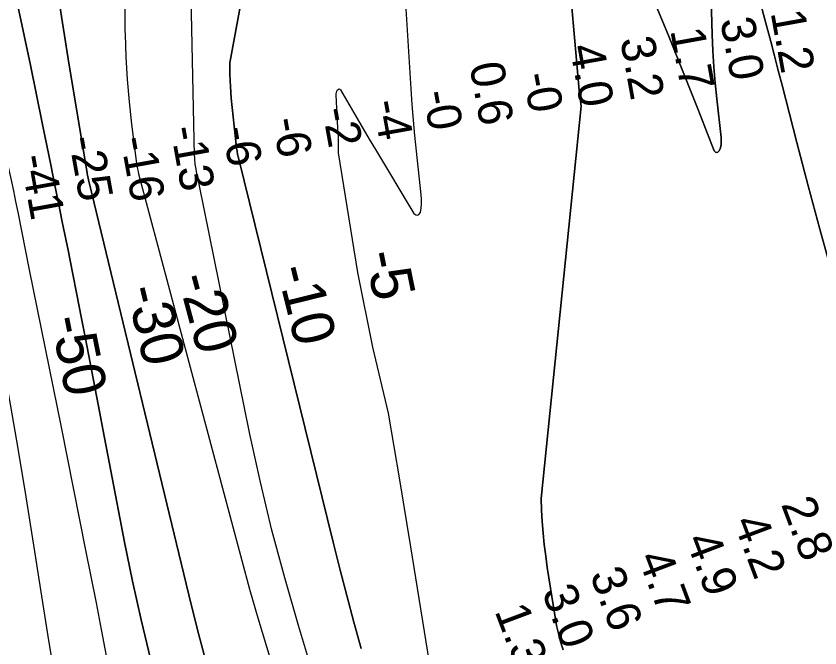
# Model space of a CAD drawing. Extents: x 3297753 to 3335611, y 652252 to 677623.
# Drawn here: x 3308796 to 3310374, y 672962 to 674202 of the extents above; entities that cross this region are included whole.
import ezdxf

# ---------------------------------------------------------------- set-up
doc = ezdxf.new("R2010")
doc.units = 0
for name, color, linetype in [('V-RIVR-EDGE', 7, 'Continuous'), ('V-RIVR-RANG', 7, 'Continuous'), ('V-TOPO-DPTH', 7, 'Continuous'), ('V-TOPO-MAJR', 7, 'Continuous'), ('V-TOPO-MAJR-IDEN', 7, 'Continuous'), ('V-TOPO-MINR', 7, 'Continuous'), ('V-TOPO-MINR-IDEN', 7, 'Continuous'), ('V-TOPO-WATR', 7, 'Continuous')]:
    doc.layers.add(name, color=color, linetype=linetype)

msp = doc.modelspace()

# ---------------------------------------------------------------- linework, layer by layer
at = {"layer": 'V-RIVR-EDGE'}
msp.add_spline([(3307850.6, 675821), (3307850.8, 675819.3), (3307852.4, 675798.5), (3307852.3, 675791.1), (3307856.9, 675791.5), (3307860.2, 675784), (3307858.1, 675766.6), (3307858, 675745.9), (3307859.7, 675743.8), (3307863.4, 675743), (3307863.4, 675739.6), (3307862.9, 675721), (3307866.2, 675694), (3307864.5, 675668.3), (3307864.8, 675653.4), (3307866, 675632.3), (3307866, 675608.2), (3307860.9, 675578), (3307855, 675536.2), (3307852, 675491), (3307848.6, 675457.4), (3307845.6, 675420.9), (3307843.1, 675401.9), (3307841.8, 675387.8), (3307842.2, 675364.6), (3307841.7, 675337.2), (3307844.1, 675320.6), (3307845.7, 675299.9), (3307849, 675263), (3307851.4, 675230.3), (3307851.7, 675205), (3307854.1, 675179.3), (3307857, 675154), (3307856.5, 675138.2), (3307855.7, 675135.8), (3307856.1, 675118.3), (3307855.6, 675111.7), (3307854.4, 675096), (3307852.6, 675077.7), (3307852.2, 675054.1), (3307855.4, 675031.7), (3307862.4, 674991.5), (3307864.8, 674962.5), (3307868.4, 674926), (3307870, 674906.1), (3307872.5, 674875), (3307874.1, 674859.3), (3307876.5, 674843.5), (3307878.9, 674816.1), (3307882.5, 674757.7), (3307886.1, 674712.5), (3307885.7, 674704.2), (3307884.5, 674698), (3307884.4, 674691.8), (3307887.3, 674680.2), (3307887.3, 674669), (3307887.3, 674658.2), (3307885.6, 674651.2), (3307881, 674644.1), (3307881, 674640), (3307886.3, 674626.3), (3307890, 674605.5), (3307895.8, 674578.6), (3307899.4, 674550.8), (3307909.3, 674510.6), (3307914.6, 674482), (3307918.3, 674453.8), (3307918.2, 674440.5), (3307919.9, 674433.9), (3307927.3, 674423.1), (3307927.3, 674417.7), (3307927.2, 674404), (3307928.5, 674400.3), (3307931.8, 674393.2), (3307935.1, 674376.6), (3307944.5, 674357.6), (3307954.9, 674337.2), (3307963.9, 674316.1), (3307975.4, 674271.7), (3307986.5, 674225.2), (3308000.1, 674178.8), (3308007.4, 674148.9), (3308015.2, 674108.3), (3308020.5, 674078.4), (3308024.2, 674072.2), (3308025, 674059.3), (3308025.4, 674039.4), (3308027.8, 673997.2), (3308030.6, 673971.5), (3308027.7, 673955.3), (3308027.2, 673943.3), (3308027.6, 673935.8), (3308029.7, 673925.4), (3308035.5, 673911.8), (3308035.4, 673899.3), (3308034.1, 673873.2), (3308036.1, 673851.2), (3308038.5, 673818.9), (3308041, 673799), (3308046.8, 673788.2), (3308050.5, 673778.3), (3308048.8, 673772.5), (3308048.8, 673761.3), (3308053.7, 673740.5), (3308060.7, 673711.1), (3308069.7, 673678.7), (3308069.7, 673665.1), (3308067.1, 673653.5), (3308067.6, 673650.1), (3308072.9, 673649.3), (3308077.9, 673648.9), (3308080, 673646.4), (3308086.5, 673608.6), (3308091.8, 673582.1), (3308104.6, 673536.5), (3308114.8, 673495), (3308121.4, 673461), (3308123.8, 673446.1), (3308128, 673436.1), (3308140.3, 673406.2), (3308148.9, 673377.2), (3308153, 673357.7), (3308158.3, 673321.2), (3308169, 673273.1), (3308189.1, 673188.1), (3308196.9, 673150.4), (3308208, 673103.9), (3308212, 673079.5), (3308214.1, 673060), (3308216.5, 673045), (3308219, 673035.9), (3308226, 673025.5), (3308228.5, 673016), (3308228.4, 673002.3), (3308230.5, 672996.9), (3308235, 672992.8), (3308235, 672984.5), (3308237.5, 672972.9), (3308242, 672953.4), (3308247.3, 672933.1), (3308253.9, 672910.7), (3308257.6, 672901.5), (3308263.8, 672890.3), (3308276.2, 672865), (3308277.4, 672856.3), (3308278.6, 672850.1), (3308283.2, 672844.3), (3308286.1, 672839.7), (3308286, 672832.2), (3308285.6, 672819), (3308288.5, 672812.3), (3308293.8, 672800.3), (3308303.7, 672777.9), (3308309.9, 672762.5), (3308316.1, 672743), (3308316.4, 672725.6), (3308318.1, 672723.1), (3308323.1, 672717.3), (3308327.6, 672706.1), (3308331.7, 672690.4), (3308330.8, 672679.6), (3308330.4, 672672.1), (3308332.5, 672667.2), (3308337.4, 672658.4), (3308343.6, 672642.7), (3308347.7, 672625.3), (3308355.9, 672595.4), (3308355.9, 672584.6), (3308357.5, 672579.6), (3308362.1, 672570.9), (3308366.6, 672563.5), (3308376.1, 672534), (3308399.6, 672478.4), (3308411.5, 672452.7), (3308418.5, 672435.2), (3308421.8, 672418.7), (3308423, 672410), (3308425.5, 672403.7), (3308428.8, 672397.5), (3308430, 672387.6), (3308434.9, 672375.5), (3308444.4, 672344.8), (3308450.6, 672327), (3308456.8, 672320.8), (3308459.7, 672312.9), (3308465.4, 672288), (3308467.4, 672268.1), (3308473.2, 672249), (3308476.1, 672236.6), (3308485.9, 672214.2), (3308490.1, 672198.8), (3308495.9, 672201.7), (3308496.7, 672193), (3308499.1, 672161.9), (3308505.2, 672134.5), (3308513.9, 672107.6), (3308522.5, 672084.8), (3308527.9, 672082.3), (3308536.2, 672087.2), (3308540.8, 672086.8), (3308539.5, 672083.9), (3308535.8, 672077.7), (3308534.9, 672067.7), (3308534.5, 672059.4), (3308532, 672050.7), (3308533.2, 672047.4), (3308536.9, 672037.9), (3308550.9, 672008.4), (3308564.9, 671974.4), (3308569.9, 671959.5), (3308576.5, 671954.9), (3308585.1, 671932.5), (3308595.9, 671910.5), (3308604.9, 671895.1), (3308605.8, 671888.5), (3308607.8, 671885.2), (3308610.7, 671881), (3308616.5, 671862.8), (3308627.6, 671838.7), (3308640.4, 671816.3), (3308661, 671765.3), (3308673, 671740.8), (3308685.3, 671715.5), (3308698.5, 671692.2), (3308700.2, 671685.6), (3308711.3, 671658.2), (3308728.2, 671627.9), (3308743.1, 671603), (3308758.3, 671575.6), (3308772, 671554.8), (3308775.3, 671548.6), (3308783.1, 671536.2), (3308790.5, 671522.9), (3308793.4, 671519.6), (3308797.2, 671517.1), (3308801.3, 671511.2), (3308803.8, 671502.9), (3308810.8, 671502.1), (3308815.8, 671499.2), (3308833.5, 671474.3), (3308845.1, 671458.5), (3308857.1, 671443.5), (3308870.7, 671429), (3308882.7, 671418.6), (3308908.8, 671397), (3308930.3, 671375.4), (3308944.3, 671361.3), (3308952.6, 671346.7), (3308960.4, 671336.8), (3308966.2, 671331.8), (3308972.8, 671328.9), (3308985.6, 671307.3), (3309001.7, 671282.4), (3309010.8, 671271.6), (3309010.8, 671268.3), (3309008.3, 671266.2), (3309011.6, 671262), (3309018.7, 671250.8), (3309024.8, 671237.1), (3309035.1, 671212.2), (3309059.5, 671169.1), (3309066.5, 671150.8), (3309067.7, 671140.5), (3309071.8, 671135.9), (3309077.2, 671128.4), (3309078.4, 671123), (3309078.4, 671117.6), (3309082.1, 671111.4), (3309089.1, 671092.7), (3309098.6, 671073.2), (3309111.4, 671045), (3309116.4, 671032.2), (3309123.3, 671011), (3309128.7, 670995.6), (3309133.2, 670984.9), (3309144, 670967.4), (3309159.7, 670945.4), (3309169.2, 670933.4), (3309182, 670924.2), (3309188.2, 670917.2), (3309197.7, 670902.2), (3309217.1, 670874.8), (3309231.6, 670859), (3309239.8, 670845.3), (3309244.8, 670840.8), (3309252.2, 670835.3), (3309260.5, 670831.2), (3309275.4, 670817.1), (3309282.4, 670810.4), (3309290.7, 670800), (3309303.1, 670788.4), (3309315.9, 670775.5), (3309335.3, 670751), (3309344.4, 670736.5), (3309351, 670726.5), (3309360.1, 670721.5), (3309375.8, 670704.9), (3309390.7, 670688.7), (3309403.1, 670668.8), (3309415.5, 670646.8), (3309426.7, 670635.1), (3309442.8, 670618.5), (3309454.3, 670603.2), (3309462.2, 670588.6), (3309470.9, 670575.3), (3309476.6, 670563.3), (3309487.4, 670558.3), (3309488.6, 670554.6), (3309489.4, 670550.8), (3309494.8, 670544.2), (3309506.8, 670533.4), (3309523.8, 670518.8), (3309530, 670506), (3309538.6, 670484.8), (3309549.7, 670453.7), (3309551.3, 670440.9), (3309555.5, 670430.9), (3309568.7, 670408.9), (3309577.3, 670396), (3309581.5, 670386.5), (3309581.5, 670383.2), (3309578.6, 670379.9), (3309576.9, 670374.9), (3309582.2, 670364.1), (3309594.6, 670336.7), (3309604.5, 670308.9), (3309606.9, 670296.1), (3309614.4, 670284.8), (3309627.2, 670267), (3309635.5, 670261.6), (3309639.2, 670259.9), (3309638.7, 670250), (3309639.5, 670236.3), (3309641.2, 670228), (3309644.9, 670221.4), (3309656.5, 670208.1), (3309664.3, 670195.6), (3309663.5, 670188.2), (3309663.8, 670176.1), (3309668, 670166.2), (3309673.3, 670159.9), (3309684.1, 670142.9), (3309690.7, 670126.3), (3309700.1, 670102.7), (3309716.7, 670076.5)], degree=3, dxfattribs=at)
at = {"layer": 'V-TOPO-DPTH'}
for points in [[(3309390.6, 675056.3), (3309215.6, 674110.2), (3309215.8, 674087.1), (3309216.9, 674064), (3309218.8, 674040.9), (3309228.3, 673949.2), (3309229, 673942.9), (3309230, 673936.6), (3309231.2, 673930.3), (3309232.6, 673924.1), (3309418.4, 673169.5), (3309431.6, 673117.2), (3309445.2, 673065), (3309459.4, 673013), (3309473.9, 672961.1)], [(3309473.9, 672961.1), (3309459.4, 673013), (3309445.2, 673065), (3309431.6, 673117.2), (3309418.4, 673169.5), (3309232.6, 673924.1), (3309231.2, 673930.3), (3309230, 673936.6), (3309229, 673942.9), (3309228.3, 673949.2), (3309218.8, 674040.9), (3309216.9, 674064), (3309215.8, 674087.1), (3309215.6, 674110.2), (3309390.6, 675056.3)], [(3310397.2, 673699), (3310373.8, 673783.7), (3310351.1, 673868.6), (3310328.8, 673953.6), (3310299.8, 674066.4), (3310292.4, 674095.1), (3310284.9, 674123.7), (3310277.4, 674152.3), (3310269.7, 674180.9), (3310198.5, 674446), (3310194.5, 674455.8), (3310189.2, 674464.6), (3310181.9, 674471.9), (3310173.2, 674478.1), (3310166.2, 674479), (3310160.4, 674477.7), (3310156.7, 674473.2), (3310154.3, 674466.5), (3310162.6, 674165.7), (3310163.9, 674134), (3310165.7, 674102.4)], [(3310165.7, 674102.4), (3310163.9, 674134), (3310162.6, 674165.7), (3310154.3, 674466.5), (3310156.7, 674473.2), (3310160.4, 674477.7), (3310166.2, 674479), (3310173.2, 674478.1), (3310181.9, 674471.9), (3310189.2, 674464.6), (3310194.5, 674455.8), (3310198.5, 674446), (3310269.7, 674180.9), (3310277.4, 674152.3), (3310284.9, 674123.7), (3310292.4, 674095.1), (3310299.8, 674066.4), (3310328.8, 673953.6), (3310351.1, 673868.6), (3310373.8, 673783.7), (3310397.2, 673699)], [(3310165.7, 674102.4), (3310168.4, 674070.9), (3310171.6, 674039.4), (3310180.2, 673963.5), (3310180.5, 673956.8), (3310180, 673950.2), (3310178.6, 673943.7), (3310176.5, 673937.3), (3310173.9, 673935), (3310171.3, 673934), (3310168.8, 673935), (3310166.3, 673937.5), (3310134.3, 674019.7), (3310120.2, 674055.8), (3310105.9, 674091.9), (3310091.3, 674127.8), (3310076.6, 674163.7), (3310016.2, 674310.2)], [(3310016.2, 674310.2), (3310076.6, 674163.7), (3310091.3, 674127.8), (3310105.9, 674091.9), (3310120.2, 674055.8), (3310134.3, 674019.7), (3310166.3, 673937.5), (3310168.8, 673935), (3310171.3, 673934), (3310173.9, 673935), (3310176.5, 673937.3), (3310178.6, 673943.7), (3310180, 673950.2), (3310180.5, 673956.8), (3310180.2, 673963.5), (3310171.6, 674039.4), (3310168.4, 674070.9), (3310165.7, 674102.4)], [(3309880.2, 674301), (3309898.6, 674086.2), (3309900, 674070.9), (3309901.6, 674055.7), (3309903.5, 674040.5), (3309905.5, 674025.3), (3309827.1, 673255.3), (3309827.9, 673232.7), (3309829.1, 673210), (3309830.9, 673187.4), (3309833.1, 673164.8), (3309835.8, 673142.3), (3309839, 673119.8), (3309854.1, 673022.6), (3309857.1, 673006.3), (3309860.7, 672990.2), (3309865.2, 672974.3), (3309870.3, 672958.5)], [(3309870.3, 672958.5), (3309865.2, 672974.3), (3309860.7, 672990.2), (3309857.1, 673006.3), (3309854.1, 673022.6), (3309839, 673119.8), (3309835.8, 673142.3), (3309833.1, 673164.8), (3309830.9, 673187.4), (3309829.1, 673210), (3309827.9, 673232.7), (3309827.1, 673255.3), (3309905.5, 674025.3), (3309903.5, 674040.5), (3309901.6, 674055.7), (3309900, 674070.9), (3309898.6, 674086.2), (3309880.2, 674301)], [(3308880.3, 674235.4), (3308898.3, 674118.3), (3308935.9, 673894), (3308936.8, 673889.3), (3308937.7, 673884.7), (3308938.7, 673880.1), (3308939.7, 673875.5), (3309125.3, 673107.2), (3309140, 673047.6), (3309155.1, 672988.1), (3309170.8, 672928.8)], [(3309170.8, 672928.8), (3309155.1, 672988.1), (3309140, 673047.6), (3309125.3, 673107.2), (3308939.7, 673875.5), (3308938.7, 673880.1), (3308937.7, 673884.7), (3308936.8, 673889.3), (3308935.9, 673894), (3308898.3, 674118.3), (3308880.3, 674235.4)], [(3308800, 674222.2), (3308812.3, 674164.1), (3308824.4, 674105.9), (3308836.3, 674047.7), (3308848.2, 673989.5), (3308856.7, 673947.7), (3308864.3, 673910.3), (3308871.8, 673873), (3308879.4, 673835.7), (3308887, 673798.4), (3308889.5, 673786), (3308898.4, 673742.5), (3308907.1, 673698.9), (3308915.7, 673655.4), (3308924.2, 673611.8), (3308932.5, 673569.3), (3308945.1, 673504.4), (3308957.6, 673439.6), (3308970.1, 673374.7), (3308982.6, 673309.8), (3309009.4, 673170), (3309024.9, 673093.4), (3309041.7, 673017), (3309060.1, 672941.1)], [(3309060.1, 672941.1), (3309041.7, 673017), (3309024.9, 673093.4), (3309009.4, 673170), (3308982.6, 673309.8), (3308970.1, 673374.7), (3308957.6, 673439.6), (3308945.1, 673504.4), (3308932.5, 673569.3), (3308924.2, 673611.8), (3308915.7, 673655.4), (3308907.1, 673698.9), (3308898.4, 673742.5), (3308889.5, 673786), (3308887, 673798.4), (3308879.4, 673835.7), (3308871.8, 673873), (3308864.3, 673910.3), (3308856.7, 673947.7), (3308848.2, 673989.5), (3308836.3, 674047.7), (3308824.4, 674105.9), (3308812.3, 674164.1), (3308800, 674222.2)], [(3309305.7, 672908.4), (3309288.2, 672964.4), (3309271.4, 673020.5), (3309255.3, 673076.9), (3309239.8, 673133.4), (3309037.5, 673891.7), (3309036.3, 673896.8), (3309035.1, 673902), (3309034.2, 673907.2), (3309033.5, 673912.4), (3309023.6, 673989.7), (3309018.7, 674033.7), (3309014.8, 674077.7), (3309012.4, 674121.8), (3309010.9, 674166), (3309010.7, 674172.8), (3309010.4, 674220.4)], [(3309305.7, 672908.4), (3309288.2, 672964.4), (3309271.4, 673020.5), (3309255.3, 673076.9), (3309239.8, 673133.4), (3309037.5, 673891.7), (3309036.3, 673896.8), (3309035.1, 673902), (3309034.2, 673907.2), (3309033.5, 673912.4), (3309023.6, 673989.7), (3309018.7, 674033.7), (3309014.8, 674077.7), (3309012.4, 674121.8), (3309010.9, 674166), (3309010.7, 674172.8), (3309010.4, 674220.4)]]:
    msp.add_lwpolyline(points, dxfattribs=at)
at = {"layer": 'V-TOPO-MAJR'}
msp.add_lwpolyline([(3308973.8, 672946.4), (3308963.9, 672998.4), (3308953.9, 673050.4), (3308943.7, 673102.3), (3308933.4, 673154.2), (3308885.2, 673395.2), (3308869.7, 673472.5), (3308854.2, 673549.8), (3308838.6, 673627), (3308823, 673704.3), (3308800.3, 673817), (3308796, 673837.9), (3308791.7, 673858.8), (3308787.2, 673879.7), (3308782.6, 673900.5), (3308753, 674033.4), (3308733, 674120.6), (3308712.4, 674207.6)], dxfattribs=at)
at = {"layer": 'V-TOPO-MINR'}
for points in [[(3309473.9, 672961.1), (3309459.4, 673013), (3309445.2, 673065), (3309431.6, 673117.2), (3309418.4, 673169.5), (3309232.6, 673924.1), (3309231.2, 673930.3), (3309230, 673936.6), (3309229, 673942.9), (3309228.3, 673949.2), (3309218.8, 674040.9), (3309216.9, 674064), (3309215.8, 674087.1), (3309215.6, 674110.2), (3309390.6, 675056.3)], [(3309611.3, 672913.3), (3309571.4, 673160.7), (3309549.8, 673291.9), (3309527.6, 673423), (3309496.4, 673552.4), (3309466.9, 673698.9), (3309429, 673933.4), (3309429.3, 673966.3), (3309428.6, 673971.8), (3309428, 673977.3), (3309427.6, 673982.8), (3309424.4, 674046.5), (3309424.5, 674049.4), (3309425, 674052.1), (3309425.9, 674054.8), (3309427.2, 674057.4), (3309430.3, 674059), (3309431.8, 674058.5), (3309433.3, 674057.2), (3309453.8, 674021.4), (3309465.6, 674000.9), (3309477.4, 673980.6), (3309489.4, 673960.2), (3309501.5, 673940), (3309577, 673814.3), (3309580.7, 673811.8), (3309584.1, 673811), (3309587.1, 673812.9), (3309589.9, 673816.4), (3309591.3, 673825.1), (3309592.2, 673833.8), (3309592.2, 673842.5), (3309591.7, 673851.3), (3309582.3, 673936.9), (3309579.2, 673967.4), (3309576.3, 673997.9), (3309573.9, 674028.5), (3309571.8, 674059.1), (3309552.8, 674363)], [(3309170.8, 672928.8), (3309155.1, 672988.1), (3309140, 673047.6), (3309125.3, 673107.2), (3308939.7, 673875.5), (3308938.7, 673880.1), (3308937.7, 673884.7), (3308936.8, 673889.3), (3308935.9, 673894), (3308898.3, 674118.3), (3308880.3, 674235.4)], [(3309402, 672836.4), (3309350.4, 673006.5), (3309323.6, 673099.5), (3309298.5, 673193), (3309276.1, 673287.2), (3309255.4, 673381.8), (3309155.6, 673872.1), (3309154.4, 673878.1), (3309153.2, 673884.1), (3309151.9, 673890.1), (3309150.7, 673896.1), (3309149.7, 673901.3), (3309149.1, 673904.7), (3309148.5, 673908.1), (3309148, 673911.5), (3309147.6, 673914.9), (3309147.3, 673918.4), (3309147, 673921.8), (3309146.9, 673925.3), (3309146.8, 673928.7), (3309139.7, 674239.7)], [(3308869, 672926.6), (3308860.5, 672976.5), (3308852.6, 673026.5), (3308844.8, 673076.4), (3308836.9, 673126.4), (3308829, 673176.4), (3308815.9, 673258.8), (3308800.8, 673349.8), (3308785.1, 673440.7), (3308768.2, 673531.5), (3308750.7, 673622.1), (3308717.3, 673788.9), (3308711.7, 673816.2), (3308705.8, 673843.5), (3308699.5, 673870.8), (3308693, 673897.9), (3308657.1, 674043.4), (3308634.1, 674134.7), (3308610.6, 674225.8)], [(3309060.1, 672941.1), (3309041.7, 673017), (3309024.9, 673093.4), (3309009.4, 673170), (3308982.6, 673309.8), (3308970.1, 673374.7), (3308957.6, 673439.6), (3308945.1, 673504.4), (3308932.5, 673569.3), (3308924.2, 673611.8), (3308915.7, 673655.4), (3308907.1, 673698.9), (3308898.4, 673742.5), (3308889.5, 673786), (3308887, 673798.4), (3308879.4, 673835.7), (3308871.8, 673873), (3308864.3, 673910.3), (3308856.7, 673947.7), (3308848.2, 673989.5), (3308836.3, 674047.7), (3308824.4, 674105.9), (3308812.3, 674164.1), (3308800, 674222.2)], [(3309305.7, 672908.4), (3309288.2, 672964.4), (3309271.4, 673020.5), (3309255.3, 673076.9), (3309239.8, 673133.4), (3309037.5, 673891.7), (3309036.3, 673896.8), (3309035.1, 673902), (3309034.2, 673907.2), (3309033.5, 673912.4), (3309023.6, 673989.7), (3309018.7, 674033.7), (3309014.8, 674077.7), (3309012.4, 674121.8), (3309010.9, 674166), (3309010.7, 674172.8), (3309010.4, 674220.4)]]:
    msp.add_lwpolyline(points, dxfattribs=at)
at = {"layer": 'V-TOPO-WATR'}
for points in [[(3310165.7, 674102.4), (3310163.9, 674134), (3310162.6, 674165.7), (3310154.3, 674466.5), (3310156.7, 674473.2), (3310160.4, 674477.7), (3310166.2, 674479), (3310173.2, 674478.1), (3310181.9, 674471.9), (3310189.2, 674464.6), (3310194.5, 674455.8), (3310198.5, 674446), (3310269.7, 674180.9), (3310277.4, 674152.3), (3310284.9, 674123.7), (3310292.4, 674095.1), (3310299.8, 674066.4), (3310328.8, 673953.6), (3310351.1, 673868.6), (3310373.8, 673783.7), (3310397.2, 673699)], [(3310016.2, 674310.2), (3310076.6, 674163.7), (3310091.3, 674127.8), (3310105.9, 674091.9), (3310120.2, 674055.8), (3310134.3, 674019.7), (3310166.3, 673937.5), (3310168.8, 673935), (3310171.3, 673934), (3310173.9, 673935), (3310176.5, 673937.3), (3310178.6, 673943.7), (3310180, 673950.2), (3310180.5, 673956.8), (3310180.2, 673963.5), (3310171.6, 674039.4), (3310168.4, 674070.9), (3310165.7, 674102.4)], [(3309870.3, 672958.5), (3309865.2, 672974.3), (3309860.7, 672990.2), (3309857.1, 673006.3), (3309854.1, 673022.6), (3309839, 673119.8), (3309835.8, 673142.3), (3309833.1, 673164.8), (3309830.9, 673187.4), (3309829.1, 673210), (3309827.9, 673232.7), (3309827.1, 673255.3), (3309905.5, 674025.3), (3309903.5, 674040.5), (3309901.6, 674055.7), (3309900, 674070.9), (3309898.6, 674086.2), (3309880.2, 674301)]]:
    msp.add_lwpolyline(points, dxfattribs=at)

# ---------------------------------------------------------------- texts
at = {"layer": 'V-RIVR-RANG'}
for s, rotation, p in [('3.0', 280.2012, (3310178.2, 674194.4)), ('1.2', 280.2012, (3310277.1, 674209)), ('1.7', 280.2012, (3310080.2, 674174.1)), ('3.2', 280.2012, (3309981.8, 674156.6)), ('4.0', 280.2012, (3309882.8, 674142)), ('0.6', 280.2012, (3309686, 674106.1)), ('-0', 280.2012, (3309791.1, 674086.9)), ('-0', 280.2012, (3309594.2, 674052)), ('-4', 280.2012, (3309495.9, 674033.5)), ('-2', 280.2012, (3309396.9, 674018.9)), ('-6', 280.2012, (3309298.9, 673998.8)), ('-13', 280.2012, (3309098.7, 673982)), ('-6', 280.2012, (3309200.5, 673981.3)), ('-25', 280.2012, (3308899.1, 673962.2)), ('-16', 280.2012, (3309000.8, 673961.5)), ('-41', 280.2012, (3308803.9, 673926.3)), ('2.8', 290.592, (3310297.3, 673244.3)), ('4.2', 290.592, (3310203.6, 673209.4)), ('4.9', 290.592, (3310109.8, 673174.7)), ('4.7', 290.592, (3310016.2, 673139.5)), ('3.6', 290.592, (3309921.9, 673106.3)), ('3.0', 290.592, (3309827.8, 673072.3)), ('1.3', 290.592, (3309735.1, 673034.7))]:
    msp.add_text(s, height=67, rotation=rotation, dxfattribs=at).set_placement(p)
at = {"layer": 'V-TOPO-MAJR-IDEN'}
msp.add_text('-50', height=83, rotation=281.3524, dxfattribs=at).set_placement((3308863.6, 673608.2))
at = {"layer": 'V-TOPO-MINR-IDEN'}
for s, rotation, p in [('-5', 281.3624, (3309480.7, 673735.9)), ('-10', 283.8315, (3309307.7, 673705.8)), ('-20', 284.9335, (3309113.2, 673688.5)), ('-30', 283.5816, (3309011.7, 673666))]:
    msp.add_text(s, height=83, rotation=rotation, dxfattribs=at).set_placement(p)

doc.saveas('drawing.dxf')
